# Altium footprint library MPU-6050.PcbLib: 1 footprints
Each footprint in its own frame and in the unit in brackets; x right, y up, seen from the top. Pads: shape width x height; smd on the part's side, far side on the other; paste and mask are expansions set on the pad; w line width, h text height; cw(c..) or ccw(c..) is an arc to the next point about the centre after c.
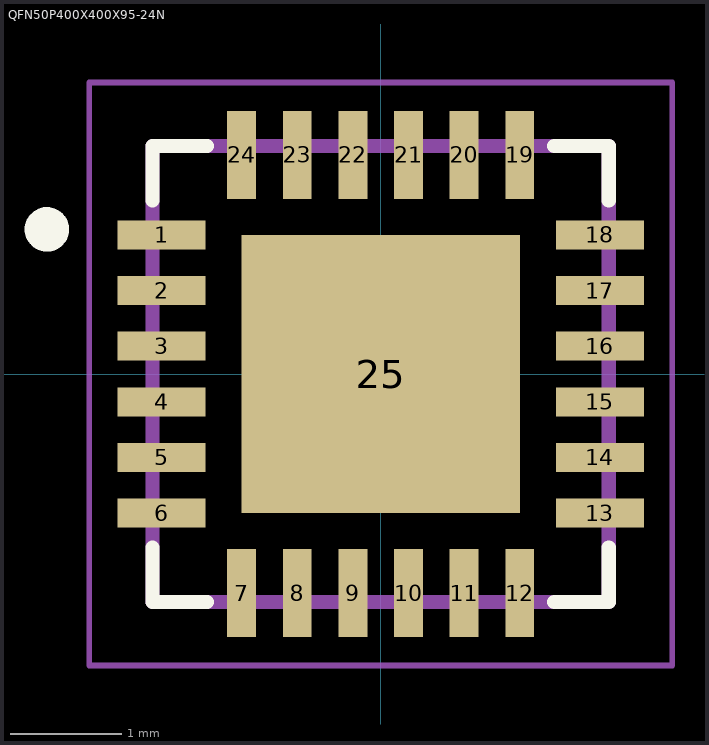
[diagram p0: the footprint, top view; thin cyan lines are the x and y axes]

## QFN50P400X400X95-24N [mm]
pads (25):
  rect 0.79x0.26 smd: 1(-1.97,1.25) 2(-1.97,0.75) 3(-1.97,0.25) 4(-1.97,-0.25) 5(-1.97,-0.75) 6(-1.97,-1.25) 13(1.97,-1.25) 14(1.97,-0.75) 15(1.97,-0.25) 16(1.97,0.25) 17(1.97,0.75) 18(1.97,1.25)
  rect 0.26x0.79 smd: 7(-1.25,-1.97) 8(-0.75,-1.97) 9(-0.25,-1.97) 10(0.25,-1.97) 11(0.75,-1.97) 12(1.25,-1.97) 19(1.25,1.97) 20(0.75,1.97) 21(0.25,1.97) 22(-0.25,1.97) 23(-0.75,1.97) 24(-1.25,1.97)
  rect 2.5x2.5 smd: 25(0,0)
Top Overlay:
  circle w0.2: c-3,1.3 r0.1
  lines w0.127: -2.05,-1.56 -2.05,-2.05 -1.56,-2.05 ; -2.05,1.56 -2.05,2.05 -1.56,2.05 ; 1.56,-2.05 2.05,-2.05 2.05,-1.56 ; 1.56,2.05 2.05,2.05 2.05,1.56
Mechanical 13:
  lines w0.127: -2.05,-2.05 -2.05,2.05 2.05,2.05 2.05,-2.05 -2.05,-2.05
Mechanical 15:
  lines w0.05: -2.62,-2.62 -2.62,2.62 2.62,2.62 2.62,-2.62 -2.62,-2.62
